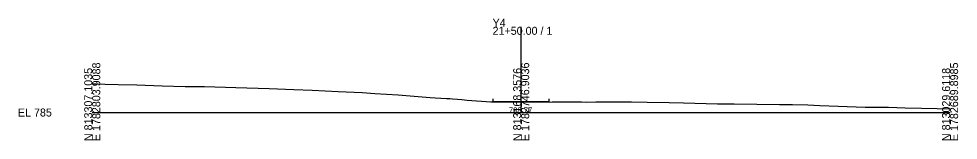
# Model space of a CAD drawing. Extents: x -26 to 3903, y -10 to 9562.
# Drawn here: x 974.3 to 1302.8, y 3990.3 to 4032.8 of the extents above; entities that cross this region are included whole.
import ezdxf

# ---------------------------------------------------------------- set-up
doc = ezdxf.new("R2010")
doc.units = 0
for name, color, linetype in [('Exist Cross Section Cell', 7, 'Continuous'), ('Exist XS Center Line Elevation Label', 7, 'Continuous'), ('Exist XS Ground Line', 7, 'Continuous'), ('Prop XS EOT Tick Mark', 7, 'Continuous'), ('Prop XS Finish Grade Pavement', 7, 'Continuous')]:
    doc.layers.add(name, color=color, linetype=linetype)

msp = doc.modelspace()

# ---------------------------------------------------------------- linework, layer by layer
at = {"layer": 'Exist Cross Section Cell'}
for p, q in [((1150, 4000), (1150, 4029.99)), ((1000, 4000), (1150, 4000)), ((1150, 4000), (1300, 4000))]:
    msp.add_line(p, q, dxfattribs=at)
at = {"layer": 'Exist XS Ground Line'}
for p, q in [((1000, 4010), (1001.23, 4009.99)), ((1001.23, 4009.99), (1004.52, 4009.91)), ((1004.52, 4009.91), (1009.03, 4009.8)), ((1009.03, 4009.8), (1015.64, 4009.64)), ((1015.64, 4009.64), (1024.49, 4009.38)), ((1024.49, 4009.38), (1032.52, 4009.14)), ((1032.52, 4009.14), (1034.87, 4009.13)), ((1034.87, 4009.13), (1039.28, 4009.09)), ((1039.28, 4009.09), (1050.17, 4008.75)), ((1050.17, 4008.75), (1061.89, 4008.36)), ((1061.89, 4008.36), (1070.55, 4008.01)), ((1070.55, 4008.01), (1076.93, 4007.78)), ((1076.93, 4007.78), (1086.03, 4007.39)), ((1086.03, 4007.39), (1094.44, 4006.97)), ((1094.44, 4006.97), (1098.85, 4006.71)), ((1098.85, 4006.71), (1106.96, 4006.18)), ((1106.96, 4006.18), (1109.73, 4005.98)), ((1109.73, 4005.98), (1118.12, 4005.31)), ((1118.12, 4005.31), (1119.96, 4005.18)), ((1119.96, 4005.18), (1123.94, 4004.96)), ((1123.94, 4004.96), (1125, 4004.86)), ((1125, 4004.86), (1125.98, 4004.8)), ((1125.98, 4004.8), (1127.69, 4004.68)), ((1127.69, 4004.68), (1129.3, 4004.56)), ((1129.3, 4004.56), (1131.16, 4004.34)), ((1131.16, 4004.34), (1139.37, 4003.76)), ((1139.37, 4003.76), (1140.16, 4003.71)), ((1140.16, 4003.71), (1140.54, 4003.71)), ((1140.54, 4003.71), (1150, 4003.77)), ((1150, 4003.77), (1150.31, 4003.77)), ((1150.31, 4003.77), (1155.1, 4003.72)), ((1155.1, 4003.72), (1159.78, 4003.68)), ((1159.78, 4003.68), (1160.18, 4003.67)), ((1160.18, 4003.67), (1160.83, 4003.71)), ((1160.83, 4003.71), (1161.81, 4003.7)), ((1161.81, 4003.7), (1167.07, 4003.69)), ((1167.07, 4003.69), (1168.94, 4003.75)), ((1168.94, 4003.75), (1171.07, 4003.72)), ((1171.07, 4003.72), (1173.02, 4003.66)), ((1173.02, 4003.66), (1176.14, 4003.72)), ((1176.14, 4003.72), (1178.94, 4003.77)), ((1178.94, 4003.77), (1183.7, 4003.73)), ((1183.7, 4003.73), (1188.58, 4003.72)), ((1188.58, 4003.72), (1194.04, 4003.64)), ((1194.04, 4003.64), (1201.77, 4003.46)), ((1201.77, 4003.46), (1206.74, 4003.35)), ((1206.74, 4003.35), (1218.62, 4003.05)), ((1218.62, 4003.05), (1219.71, 4003.02)), ((1219.71, 4003.02), (1224.48, 4002.99)), ((1224.48, 4002.99), (1240.37, 4002.85)), ((1240.37, 4002.85), (1244.88, 4002.76)), ((1244.88, 4002.76), (1250.22, 4002.64)), ((1250.22, 4002.64), (1254.39, 4002.45)), ((1254.39, 4002.45), (1260.87, 4002.27)), ((1260.87, 4002.27), (1270.32, 4001.92)), ((1270.32, 4001.92), (1272.08, 4001.91)), ((1272.08, 4001.91), (1273.15, 4001.91)), ((1273.15, 4001.91), (1274.12, 4001.88)), ((1274.12, 4001.88), (1278.45, 4001.88)), ((1278.45, 4001.88), (1284.3, 4001.69)), ((1284.3, 4001.69), (1290.04, 4001.47)), ((1290.04, 4001.47), (1295.5, 4001.43)), ((1295.5, 4001.43), (1300, 4001.31))]:
    msp.add_line(p, q, dxfattribs=at)
at = {"layer": 'Prop XS EOT Tick Mark'}
for p, q in [((1140.16, 4003.83), (1140.16, 4004.83)), ((1159.79, 4003.8), (1159.79, 4004.8))]:
    msp.add_line(p, q, dxfattribs=at)
at = {"layer": 'Prop XS Finish Grade Pavement'}
for p, q in [((1140.16, 4003.83), (1140.54, 4003.84)), ((1140.54, 4003.84), (1150, 4003.89)), ((1150, 4003.89), (1150.31, 4003.89)), ((1150.31, 4003.89), (1155.1, 4003.84)), ((1155.1, 4003.84), (1159.78, 4003.8)), ((1159.78, 4003.8), (1159.79, 4003.8))]:
    msp.add_line(p, q, dxfattribs=at)

# ---------------------------------------------------------------- texts
at = {"layer": 'Exist Cross Section Cell'}
for s, p in [('Y4', (1140, 4029.99)), ('21+50.00 / 1', (1140, 4027.19)), ('EL 785', (974, 3998.6))]:
    msp.add_text(s, height=2.8, dxfattribs=at).set_placement(p)
for s, p in [('N 813307.1035', (1000, 3990)), ('E 1782803.9088', (1002.8, 3990)), ('N 813168.3576', (1150, 3990)), ('E 1782746.9036', (1152.8, 3990)), ('N 813029.6118', (1300, 3990)), ('E 1782689.8985', (1302.8, 3990))]:
    msp.add_text(s, height=2.8, rotation=90, dxfattribs=at).set_placement(p)
at = {"layer": 'Exist XS Center Line Elevation Label'}
msp.add_text('788.77', height=2, dxfattribs=at).set_placement((1145.7, 3999.77))

doc.saveas('drawing.dxf')
